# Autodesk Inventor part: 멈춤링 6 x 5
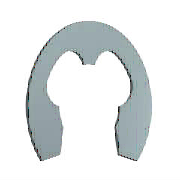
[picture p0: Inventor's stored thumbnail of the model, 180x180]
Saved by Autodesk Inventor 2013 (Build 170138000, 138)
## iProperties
Created: 2012-02
Part Number: 멈춤링 6 x 5
Material: 강철, 연강
Description: 스프링 리테이닝 링
Document SubType Name: Modeling
Standard: JIS B 2805
Designer: mduedu
Standards Organization: JIS
Language: ko-KR
Size Designation: 5
Categories: <MemberInstance><Categories><Category DisplayName="샤프트 부품" InternalName="7f7aeb1f-a693-4053-b835-cee3144e0d98" Mnemonic="SHFT"><Category DisplayName="써클립" Inter
Density: 1 g/cm^3
IsCustomPart: 1
Author: mduedu
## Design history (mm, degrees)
sketch "스케치1"
  geometry: L1 (-0.5, 0.024)-(0, 0.024) reference; L2 (-3.206, 0)-(3.486, 0) reference; L3 (-2.291, -3.976)-(2.291, -3.976); L4 (0, 1.949)-(0, -3.479) reference; L5 (-3, -1.976)-(-2.51, -1.976); L6 (-0.5, 0.024)-(-0.5, 0.509); L7 (0, 2.524)-(2.53, 2.524); L8 (-2.291, -3.976)-(-3.051, -6.131); L9 (0, -0.476)-(-1.278, -0.476); L10 (2.291, -3.976)-(3.051, -6.131); L11 (3, -1.976)-(2.51, -1.976); L12 (0.5, 0.024)-(0.5, 0.509); C1 r 3 at (0, -2.976); A1 r 2.5 centre (0, -2.976) between (-2.368, -2.174) and (-2.291, -3.976); A2 r 0.5 centre (0, 0.024) between (-0.5, 0.024) and (0.5, 0.024); A3 r 5.5 centre (0, -2.976) between (4.351, -6.34) and (-4.351, -6.34); A4 r 4 centre (0, -2.976) between (-1, 0.897) and (-3.529, -1.094); A5 r 0.4 centre (-0.9, 0.509) between (-0.5, 0.509) and (-1, 0.897); A6 r 0.6 centre (-3, -1.376) between (-3.529, -1.094) and (-3, -1.976); A7 r 0.15 centre (-2.51, -2.126) between (-2.368, -2.174) and (-2.51, -1.976); A8 r 0.75 centre (-3.758, -5.881) between (-4.351, -6.34) and (-3.051, -6.131); A9 r 0.75 centre (3.758, -5.881) between (3.051, -6.131) and (4.351, -6.34); A10 r 2.5 centre (0, -2.976) between (2.291, -3.976) and (2.368, -2.174); A11 r 0.15 centre (2.51, -2.126) between (2.51, -1.976) and (2.368, -2.174); A12 r 0.6 centre (3, -1.376) between (3, -1.976) and (3.529, -1.094); A13 r 4 centre (0, -2.976) between (3.529, -1.094) and (1, 0.897); A14 r 0.4 centre (0.9, 0.509) between (1, 0.897) and (0.5, 0.509); 1 further point
  constraints: 30 point on circle, 20 end point, 15 centre point, 13 symmetric about line, 12 tangent, 8 point on line, 4 parallel, 2 coincident, 2 horizontal, 1 concentric, 1 perpendicular, 1 vertical alignment, 9 other
  dimensions: "d0" = 6 diameter of C1 (= WD); "d3" = 1 distance from line of A1.centre L3 (= 0.2 x ND); "d4" = 0.5 radius of A2 (= 0.1 x ND); "d5" = 11 diameter of A3 (= SD2); "d8" = 4 radius of A4 (= 0.8 x ND); "d9" = 1 distance from line of A1.centre L5 (= 0.2 x ND); "d10" = 0.4 radius of A5 (= 0.08 x ND); "d11" = 0.6 radius of A6 (= 0.12 x ND); "d12" = 0.15 radius of A7 (= 0.03 x ND); "d13" = 0.75 radius of A8 (= 0.15 x ND); "d14" = 2.5 distance from line of A1.centre L9 (= 0.5 x ND); "d15" = 2.5 radius of A1 (= 0.5 x ND)
extrude "본체" new body sketch "스케치1" distance "d16" = 0.6 (= SD); taper "d17" = 0 deg
workaxis "Work Axis1"
workaxis "Work Axis2"
workplane "Work Plane1"
body "Solid1"
other parameters: "ND" = 5 [user parameter; used in 14 equation terms], "SD" = 0.6 [user parameter; used in 1 equation term], "WD" = 6 (= WDMIN) [user parameter; used in 1 equation term], "d1" = 8 (= 1.6 x ND), "d2" = 5 (= ND), "SD2" = 11 [user parameter; used in 1 equation term], "d6" = 5 (= ND), "d7" = 0.75 (= 0.15 x ND), "d18" = 0, "d19" = 0, "d27" = 0, "d28" = 0, "WDMIN" = 6 [user parameter; used in 1 equation term], "SNB" = 0.7 [user parameter], "WDMAX" = 8 [user parameter], "BUBRMI" = 1.2 [user parameter]
